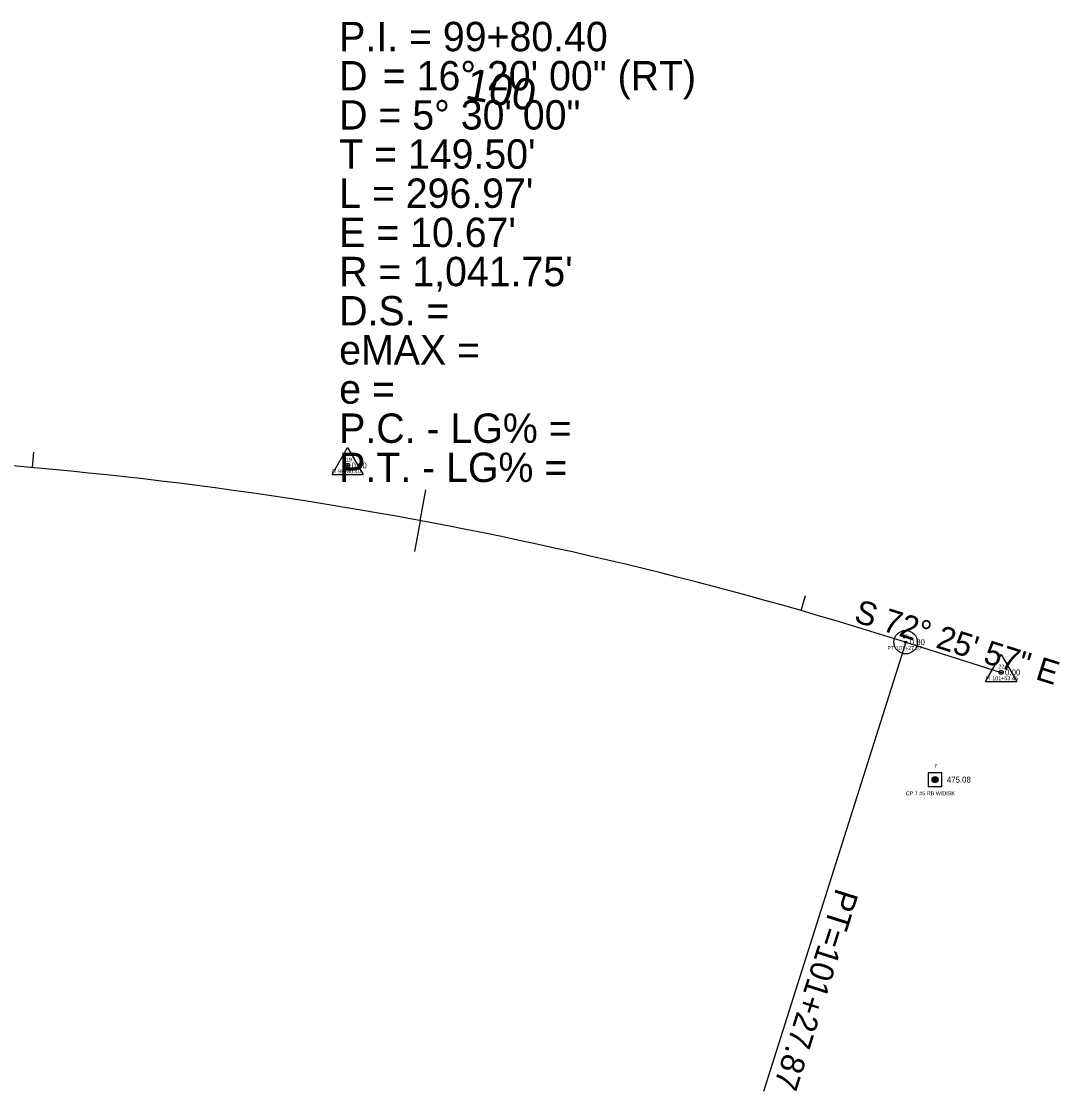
# Model space of a CAD drawing. Extents: x 1809463 to 1812121, y 790645 to 791946.
# Drawn here: x 1811493.8 to 1811759, y 790979.4 to 791252.6 of the extents above; entities that cross this region are included whole.
import ezdxf

# ---------------------------------------------------------------- set-up
doc = ezdxf.new("R2010")
doc.units = 0
for name, color, linetype in [('RD_HC_Cl', 7, 'Continuous'), ('RD_HC_Data', 7, 'Continuous'), ('RD_HC_Data_Tic', 7, 'Continuous'), ('RD_HC_Survey', 7, 'Continuous'), ('RD_HC_Survey_ELEV', 7, 'Continuous'), ('RD_HC_Survey_txCode', 7, 'Continuous'), ('RD_HC_TX_Sta50', 7, 'Continuous'), ('RD_HC_txCode', 7, 'Continuous'), ('RD_SMD_Locator', 7, 'Continuous')]:
    doc.layers.add(name, color=color, linetype=linetype)

msp = doc.modelspace()

# ---------------------------------------------------------------- linework, layer by layer
at = {"layer": 'RD_HC_Cl'}
msp.add_line((1811719.68, 791094.11), (1811744.06, 791086.39), dxfattribs=at)
msp.add_arc((1811405.24, 790100.94), 1041.75, 72.43242, 88.76562, dxfattribs=at)
at = {"layer": 'RD_HC_Data'}
for p, q in [((1811573.18, 791136.94), (1811577.15, 791143.82)), ((1811577.15, 791143.82), (1811581.12, 791136.94)), ((1811573.18, 791136.94), (1811581.12, 791136.94)), ((1811719.68, 791094.11), (1811683.35, 790979.36)), ((1811740.09, 791084.09), (1811744.06, 791090.97)), ((1811744.06, 791090.97), (1811748.03, 791084.09)), ((1811740.09, 791084.09), (1811748.03, 791084.09))]:
    msp.add_line(p, q, dxfattribs=at)
for centre, radius in [((1811577.15, 791139.23), 0.529), ((1811719.68, 791094.11), 3), ((1811719.68, 791094.11), 0.282), ((1811744.06, 791086.39), 0.529)]:
    msp.add_circle(centre, radius, dxfattribs=at)
at = {"layer": 'RD_HC_Data_Tic'}
for p, q in [((1811496.67, 791138.67), (1811497.02, 791142.66)), ((1811595.71, 791125.13), (1811597.17, 791133)), ((1811595.71, 791125.13), (1811594.25, 791117.27)), ((1811693, 791102.16), (1811694.1, 791106.01))]:
    msp.add_line(p, q, dxfattribs=at)
at = {"layer": 'RD_HC_Survey'}
for p, q in [((1811726.44, 791058.83), (1811726.44, 791059.19)), ((1811726.46, 791058.75), (1811726.46, 791059.28)), ((1811726.49, 791058.69), (1811726.49, 791059.34)), ((1811726.51, 791058.64), (1811726.51, 791059.38)), ((1811726.54, 791058.6), (1811726.54, 791059.43)), ((1811726.56, 791058.56), (1811726.56, 791059.46)), ((1811726.59, 791058.53), (1811726.59, 791059.5)), ((1811726.61, 791058.5), (1811726.61, 791059.52)), ((1811726.64, 791058.48), (1811726.64, 791059.55)), ((1811726.66, 791058.45), (1811726.66, 791059.58)), ((1811726.69, 791058.43), (1811726.69, 791059.6)), ((1811726.71, 791058.41), (1811726.71, 791059.62)), ((1811726.74, 791058.39), (1811726.74, 791059.64)), ((1811726.76, 791058.37), (1811726.76, 791059.65)), ((1811726.79, 791058.36), (1811726.79, 791059.67)), ((1811726.81, 791058.34), (1811726.81, 791059.68)), ((1811726.84, 791058.33), (1811726.84, 791059.7)), ((1811726.86, 791058.32), (1811726.86, 791059.71)), ((1811726.88, 791058.31), (1811726.88, 791059.72)), ((1811726.91, 791058.3), (1811726.91, 791059.73)), ((1811726.93, 791058.29), (1811726.93, 791059.74)), ((1811726.96, 791058.28), (1811726.96, 791059.75)), ((1811726.98, 791058.27), (1811726.98, 791059.76)), ((1811727.01, 791058.27), (1811727.01, 791059.76)), ((1811727.03, 791058.26), (1811727.03, 791059.77)), ((1811727.06, 791058.26), (1811727.06, 791059.77)), ((1811727.08, 791058.25), (1811727.08, 791059.78)), ((1811727.11, 791058.25), (1811727.11, 791059.78)), ((1811727.13, 791058.25), (1811727.13, 791059.78)), ((1811727.16, 791058.24), (1811727.16, 791059.78)), ((1811727.18, 791058.24), (1811727.18, 791059.78)), ((1811727.21, 791058.24), (1811727.21, 791059.78)), ((1811727.23, 791058.25), (1811727.23, 791059.78)), ((1811727.26, 791058.25), (1811727.26, 791059.78)), ((1811727.28, 791058.25), (1811727.28, 791059.78)), ((1811727.31, 791058.25), (1811727.31, 791059.77)), ((1811727.33, 791058.26), (1811727.33, 791059.77)), ((1811727.35, 791058.26), (1811727.35, 791059.76)), ((1811727.38, 791058.27), (1811727.38, 791059.76)), ((1811727.4, 791058.28), (1811727.4, 791059.75)), ((1811727.43, 791058.28), (1811727.43, 791059.74)), ((1811727.45, 791058.29), (1811727.45, 791059.74)), ((1811727.48, 791058.3), (1811727.48, 791059.73)), ((1811727.5, 791058.31), (1811727.5, 791059.72)), ((1811727.53, 791058.32), (1811727.53, 791059.7)), ((1811727.55, 791058.34), (1811727.55, 791059.69)), ((1811727.58, 791058.35), (1811727.58, 791059.68)), ((1811727.6, 791058.37), (1811727.6, 791059.66)), ((1811727.63, 791058.38), (1811727.63, 791059.65)), ((1811727.65, 791058.4), (1811727.65, 791059.63)), ((1811727.68, 791058.42), (1811727.68, 791059.61)), ((1811727.7, 791058.44), (1811727.7, 791059.59)), ((1811727.73, 791058.46), (1811727.73, 791059.56)), ((1811727.75, 791058.49), (1811727.75, 791059.54)), ((1811727.78, 791058.52), (1811727.78, 791059.51)), ((1811727.8, 791058.55), (1811727.8, 791059.48)), ((1811727.83, 791058.58), (1811727.83, 791059.44)), ((1811727.85, 791058.62), (1811727.85, 791059.41)), ((1811727.87, 791058.67), (1811727.87, 791059.36)), ((1811727.9, 791058.72), (1811727.9, 791059.31)), ((1811727.92, 791058.79), (1811727.92, 791059.24)), ((1811727.95, 791058.9), (1811727.95, 791059.13))]:
    msp.add_line(p, q, dxfattribs=at)
msp.add_lwpolyline([(1811728.94, 791060.76), (1811725.44, 791060.76), (1811725.44, 791057.26), (1811728.94, 791057.26)], close=True, dxfattribs=at)
msp.add_circle((1811727.19, 791059.01), 0.769, dxfattribs=at)
at = {"layer": 'RD_SMD_Locator'}
for centre in [(1811577.15, 791139.23), (1811719.68, 791094.11), (1811744.06, 791086.39), (1811727.19, 791059.01)]:
    msp.add_circle(centre, 0.15, dxfattribs=at)

# ---------------------------------------------------------------- texts
at = {"layer": 'RD_HC_Data'}
for s, p in [('P.I. = 99+80.40', (1811575, 791245)), ('D', (1811575, 791235)), ('    = 16%%d 20\' 00" (RT)', (1811575, 791235)), ('D = 5%%d 30\' 00"', (1811575, 791225)), ("T = 149.50'", (1811575, 791215)), ("L = 296.97'", (1811575, 791205)), ("E = 10.67'", (1811575, 791195)), ("R = 1,041.75'", (1811575, 791185)), ('D.S. = ', (1811575, 791175)), ('eMAX = ', (1811575, 791165)), ('e = ', (1811575, 791155)), ('P.C. - LG% = ', (1811575, 791145)), ('P.T. - LG% = ', (1811575, 791135))]:
    msp.add_text(s, height=7.5, dxfattribs=at).set_placement(p)
for s, rotation, p in [('S 72%%d 25\' 57" E', 342.4324, (1811706.2, 791099.42)), ('PT=101+27.87', 252.4324, (1811701.96, 791031.54))]:
    msp.add_text(s, height=6, rotation=rotation, dxfattribs=at).set_placement(p)
at = {"layer": 'RD_HC_Survey_ELEV'}
for s, p in [('0.00', (1811578.15, 791138.48)), ('0.00', (1811720.68, 791093.36)), ('0.00', (1811745.06, 791085.64)), ('475.08', (1811730.19, 791058.26))]:
    msp.add_text(s, height=1.5, dxfattribs=at).set_placement(p)
at = {"layer": 'RD_HC_Survey_txCode'}
for s, p in [('7', (1811726.9, 791062.01)), ('CP 7 #5 RB W/DISK', (1811719.69, 791055.01))]:
    msp.add_text(s, height=1, dxfattribs=at).set_placement(p)
at = {"layer": 'RD_HC_TX_Sta50'}
msp.add_text('100', height=8, rotation=349.4651, dxfattribs=at).set_placement((1811606.87, 791232.91))
at = {"layer": 'RD_HC_txCode'}
for s, p in [('19', (1811576.7, 791140.23)), ('PI 99+80.40', (1811573.01, 791137.23)), ('20', (1811718.9, 791095.11)), ('PT 101+27.87', (1811715.05, 791092.11)), ('22', (1811743.33, 791087.39)), ('PI 101+53.45', (1811740.08, 791084.39))]:
    msp.add_text(s, height=1, dxfattribs=at).set_placement(p)

doc.saveas('drawing.dxf')
